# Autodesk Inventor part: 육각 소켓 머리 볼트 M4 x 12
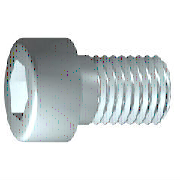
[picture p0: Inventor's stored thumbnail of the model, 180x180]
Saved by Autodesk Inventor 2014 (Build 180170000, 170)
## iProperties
IsCustomPart: 1
Created: 2012-02
Part Number: 육각 소켓 머리 볼트 M4 x 12
Material: 스테인리스강
Description: 6각 소켓 머리 캡 나사
Document SubType Name: Modeling
Standard: ISO 4762
Designer: mdu-01
Standard Revision: Fourth edition 2004-03-01
Standards Organization: ISO
Language: ko-KR
Size Designation: M4 x 12
Categories: <MemberInstance><Categories><Category DisplayName="조임쇠" InternalName="e4da775c-781d-43d5-af7c-5136215cf5a6" Mnemonic="FSTN"><Category DisplayName="볼트" InternalN
Density: 8.08 g/cm^3
Mass: 2.29719 g
Surface Area: 3.30853 cm^2
Volume: 0.284306 cm^3
Appearance: 반광택
Author: mdu-01
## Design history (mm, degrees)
sketch "스케치1"
  geometry: L1 (-1, 0)-(12, 0); L2 (12, 0)-(12, 2); L3 (12, 2)-(1.75, 2); L4 (1.75, 2)-(1.32, 2); L5 (1.32, 2)-(0, 2); L6 (0, 2)-(0, 3.5); L7 (0, 3.5)-(-4, 3.5); L8 (-4, 3.5)-(-4, 1.732); L9 (-4, 1.732)-(-2, 1.732); L10 (-2, 1.732)-(-1, 0); L11 (-7.2, 0)-(15.2, 0) reference; L12 (0, -0.7)-(0, 4.2) reference; L13 (1.75, 2)-(0, 2)
  constraints: 22 end point, 6 parallel, 2 collinear, 2 perpendicular, 1 horizontal, 1 point on line
  dimensions: "d1" = 10.25 distance from line of L3.end L2 (= GEL); "d2" = 0.42952 distance of L4.end L3.end (computed from GAL); "d3" = 4 distance between parallel lines of L8 L6 (= KOH); "d4" = 2 distance of L8.end L9.end (= INTI); "d5" = 60 deg angle of L10 L1; "d6" = 4 diameter of L3 L1 (= GD); "d7" = 4 diameter of L5 L1 (= BDM); "d8" = 3.4641 diameter of L9 L1 (= 1.1547 x SW); "d9" = 7 diameter of L7 L1 (= KOD); "d26" = 12 distance between parallel lines of L12 L2 (= NLG)
revolve "본체" sketch "스케치1" stored, may be unused: angle "d10" = 90 deg
sketch "스케치2"
  geometry: L1 (0, -4.9)-(0, 4.9) reference; L2 (-4.9, 0)-(4.9, 0) reference; L3 (1.732, 0)-(0.866, -1.5); L4 (0.866, -1.5)-(-0.866, -1.5); L5 (-0.866, -1.5)-(-1.732, 0); L6 (-1.732, 0)-(-0.866, 1.5); L7 (-0.866, 1.5)-(0.866, 1.5); L8 (0.866, 1.5)-(1.732, 0); 2 further points
  constraints: 12 end point, 1 coincident, 1 horizontal alignment, 1 point on line, 12 other
extrude "슬롯" join sketch "스케치2" stored distance "d11" = 10; taper "d12" = 0 deg
workplane "Work Plane1"
fillet "Fillet2" dims "d30" = 0.1 (= R)
body "Solid1"
fillet "모깎기1" dims "d17" = 0.4 (= RR)
feature "스레드" dims "d13" = 10.25 (= GEL), "d14" = 0
chamfer "모따기1" distance "d15" = 0.42941 (= -0.5 x SPD + 0.5 x GD); stored, may be unused: second distance "d16" = 0.42941 (= GUL), angle "d27" = 45 deg
other parameters: "GD" = 4 [user parameter; used in 2 equation terms], "NLG" = 12 [user parameter; used in 1 equation term], "GEL" = 10.25 [user parameter; used in 2 equation terms], "KOD" = 7 [user parameter; used in 1 equation term], "KOH" = 4 [user parameter; used in 1 equation term], "INTI" = 2 [user parameter; used in 1 equation term], "GAL" = 0.42941 (= 0.61345 x PTC) [user parameter; used in 1 equation term], "GUL" = 0.42941 (= 0.61345 x PTC) [user parameter; used in 1 equation term], "BDM" = 4 (= NND) [user parameter; used in 1 equation term], "SW" = 3 [user parameter; used in 2 equation terms], "RR" = 0.4 [user parameter; used in 1 equation term], "SPD" = 3.14117 (= NND - 1.2269 x PTC) [user parameter; used in 1 equation term], "d19" = 0, "d28" = 0, "d29" = 0, "R" = 0.1 [user parameter; used in 1 equation term], "TOA" = 30 deg [user parameter], "GD1" = 3.14117 (= THREADDIA - 1.2269 x PTC) [user parameter], "THREADDIA" = 4 [user parameter; used in 1 equation term], "FAWI" = 45 deg [user parameter], "TPU" = 14.28571 (computed from PTC) [user parameter], "PTC" = 0.7 [user parameter; used in 5 equation terms], "NND" = 4 [user parameter; used in 2 equation terms], "E0" = 3.465 (= 1.155 x SW) [user parameter]
